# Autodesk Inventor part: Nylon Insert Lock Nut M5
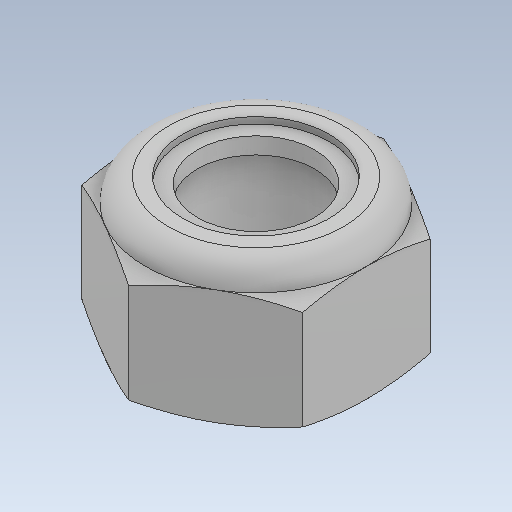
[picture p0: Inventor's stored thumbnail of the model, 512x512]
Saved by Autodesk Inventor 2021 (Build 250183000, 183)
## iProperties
Created: 2026-10
Part Number: Nylon Insert Lock Nut M5
Material: Steel
Document SubType Name: Modeling
Designer: hp
Density: 7.85 g/cm^3
Appearance: Default
Author: hp
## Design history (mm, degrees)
feature "Body1"
body "Solid1"
